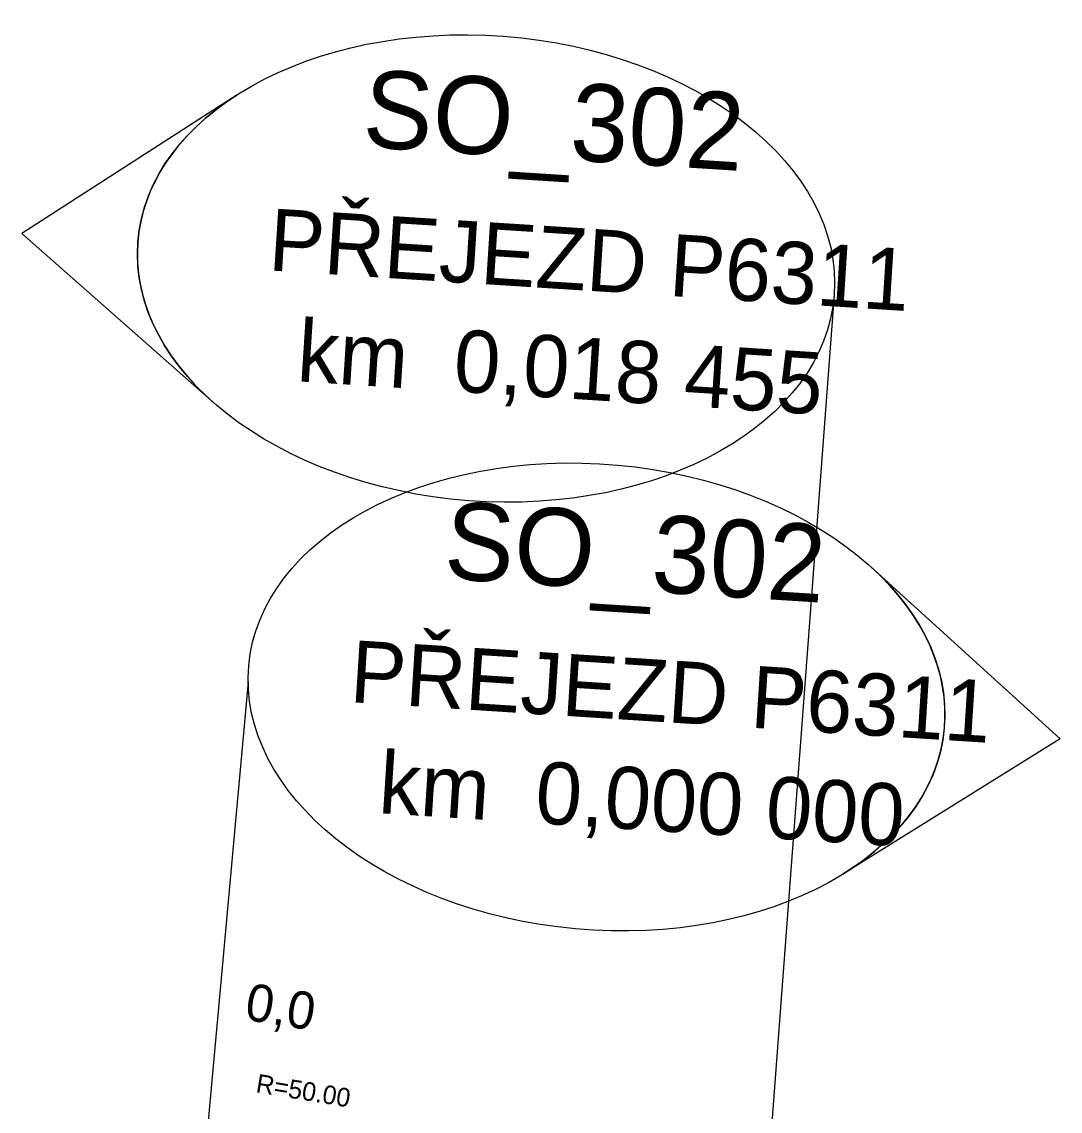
# Model space of a CAD drawing. Extents: x -743186.9 to -743133.1, y -1127113.3 to -1127042.8.
# Drawn here: x -743186.85 to -743153.4, y -1127077.93 to -1127042.84 of the extents above; entities that cross this region are included whole.
import ezdxf

# ---------------------------------------------------------------- set-up
doc = ezdxf.new("R2010")
doc.units = 0
for name, color, linetype in [('_Násyp', 7, 'Continuous'), ('bublina_fialová_čára_tenká', 7, 'Continuous'), ('bublina_růžová_230_čára_tučná', 7, 'Continuous'), ('OSA_POP', 7, 'Continuous'), ('SKLONOVNIKY', 7, 'Continuous')]:
    doc.layers.add(name, color=color, linetype=linetype)

msp = doc.modelspace()

# ---------------------------------------------------------------- linework, layer by layer
at = {"layer": 'bublina_fialová_čára_tenká'}
for p, q in [((-743160.679, -1127051.634), (-743164.286, -1127099.423)), ((-743179.562, -1127064.096), (-743182.5, -1127096.45))]:
    msp.add_line(p, q, dxfattribs=at)
at = {"layer": 'bublina_růžová_230_čára_tučná'}
for p, q in [((-743179.913, -1127045.19), (-743186.854, -1127049.658)), ((-743179.913, -1127045.19), (-743186.854, -1127049.658)), ((-743186.854, -1127049.658), (-743180.663, -1127055.117)), ((-743186.854, -1127049.658), (-743180.663, -1127055.117)), ((-743159.51, -1127060.384), (-743153.397, -1127065.932)), ((-743159.51, -1127060.384), (-743153.397, -1127065.932)), ((-743153.397, -1127065.932), (-743160.402, -1127070.299)), ((-743153.397, -1127065.932), (-743160.402, -1127070.299))]:
    msp.add_line(p, q, dxfattribs=at)
for centre, major_axis in [((-743171.897, -1127050.787), (11.218, -0.847)), ((-743168.337, -1127064.588), (-11.205, 1.008))]:
    msp.add_ellipse(centre, major_axis=major_axis, ratio=0.666667, dxfattribs=at)
for centre, major_axis in [((-743171.897, -1127050.787), (-11.22, 0.847)), ((-743168.337, -1127064.588), (11.206, -1.008))]:
    msp.add_ellipse(centre, major_axis=major_axis, ratio=0.666473, start_param=5.557317, end_param=7.009053, dxfattribs=at)

# ---------------------------------------------------------------- texts
at = {"layer": '_Násyp'}
for s, height, p in [('SO_302', 2.5, (-743175.908, -1127046.867)), ('PŘEJEZD P6311', 2, (-743178.937, -1127050.846)), ('km  0,018 455', 2, (-743178.022, -1127054.419)), ('SO_302', 2.5, (-743173.286, -1127060.774)), ('PŘEJEZD P6311', 2, (-743176.314, -1127064.752)), ('km  0,000 000', 2, (-743175.393, -1127068.327))]:
    msp.add_text(s, height=height, rotation=356.3528, dxfattribs=at).set_placement(p)
at = {"layer": 'OSA_POP'}
msp.add_text('0,0', height=1.2, rotation=350.752, dxfattribs=at).set_placement((-743179.708, -1127074.975))
at = {"layer": 'SKLONOVNIKY'}
msp.add_text('R=50.00', height=0.6, rotation=350.752, dxfattribs=at).set_placement((-743179.337, -1127077.318))

doc.saveas('drawing.dxf')
